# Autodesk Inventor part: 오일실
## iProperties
Created: 2014-07
Part Number: 오일실
Material: 고무
Description: 오일-실
Document SubType Name: Modeling
Standard: KS B 2804
Designer: KYOUNG IL JANG
Standards Organization: KS
Language: ko-KR
Size Designation: D - 10 20 7
Categories: <MemberInstance><Categories><Category DisplayName="샤프트 부품" InternalName="7f7aeb1f-a693-4053-b835-cee3144e0d98" Mnemonic="SHFT"><Category DisplayName="실링" Intern
Density: 0.93 g/cm^3
Company: 한국ATC센터
IsCustomPart: 0
Author: KYOUNG IL JANG
